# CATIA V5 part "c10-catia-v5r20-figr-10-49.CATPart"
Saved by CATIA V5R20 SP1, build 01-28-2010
Part number: Part1
Bounding box of the stored display mesh (mm): x -45.985 to 45.985, y -45.985 to 45.985, z -55 to 3.515
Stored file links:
  D:\v5_r20\psrt_files_downloaded\c10\c10-catia-v5r20-figr-10-49.CATPart
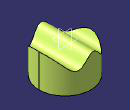
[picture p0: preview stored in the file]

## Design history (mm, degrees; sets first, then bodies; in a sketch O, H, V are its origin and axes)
Set1
  Sketch1 on xy-plane, origin (0, 0, 0), H (-1, 0, 0), V (0, -1, 0)
    circle A1 centre (0, 0) radius 45.985
  Extrude1: Element1 Sketch1, Lim1 56, Lim2 55, Direction xy-plane
  Sketch2 on zx-plane, origin (0, 0, 0), H (1, 0, 0), V (0, 0, -1)
    spline S1 through (-80.5635, 24.8913) (-73.6025, 19.8803) (-54.8525, -3.3629) (-35.1982, 19.8803) (-2.6271, -1.6506) (16.6996, 17.2854) (52.4104, -6.7877) (63.5409, 1.5862)
  Extrude2: Element1 Sketch2, Lim1 72, Lim2 69, Direction Sketch1.V
  Split1: ToCut Extrude1, Cutting Extrude2
  Trim1: Element1 Extrude1, Element2 Extrude2
  Trim2: Element1 Extrude1, Element2 Extrude2
Body1 (main body)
